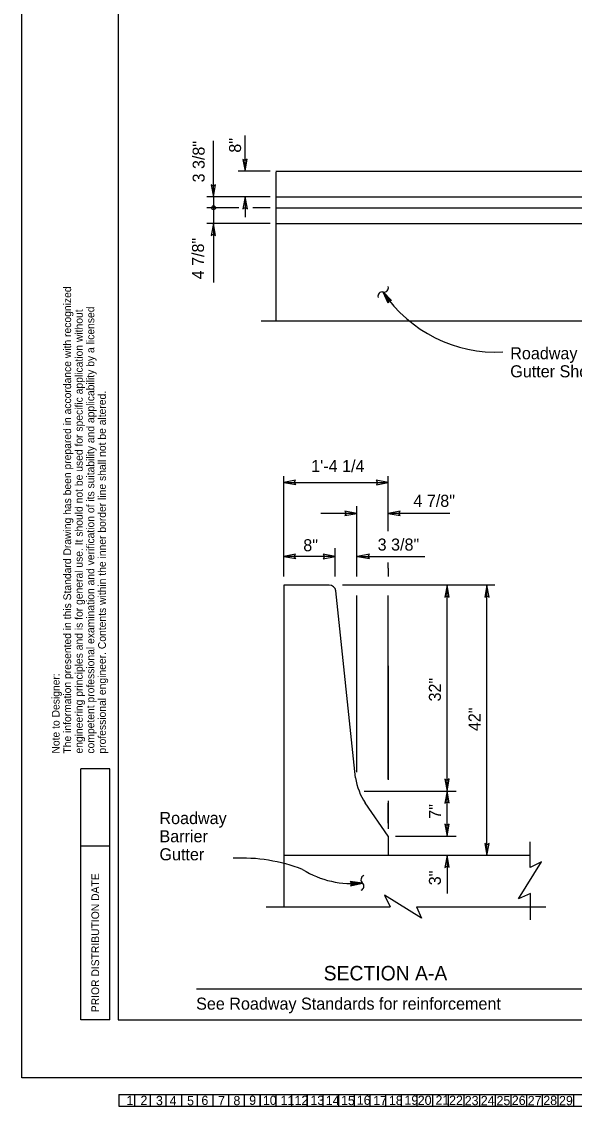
# Model space of a CAD drawing. Extents: x 0 to 2.83, y -0.03 to 1.83.
# Drawn here: x 0 to 0.597, y -0.031 to 1.14 of the extents above; entities that cross this region are included whole.
import ezdxf

# ---------------------------------------------------------------- set-up
doc = ezdxf.new("R2010")
doc.units = 0
for name, color, linetype in [('1', 7, 'Continuous'), ('10', 7, 'Continuous'), ('11', 7, 'Continuous'), ('12', 7, 'Continuous'), ('13', 7, 'Continuous'), ('14', 7, 'Continuous'), ('15', 7, 'Continuous'), ('16', 7, 'Continuous'), ('17', 7, 'Continuous'), ('18', 7, 'Continuous'), ('19', 7, 'Continuous'), ('2', 7, 'Continuous'), ('20', 7, 'Continuous'), ('21', 7, 'Continuous'), ('22', 7, 'Continuous'), ('23', 7, 'Continuous'), ('24', 7, 'Continuous'), ('25', 7, 'Continuous'), ('26', 7, 'Continuous'), ('27', 7, 'Continuous'), ('28', 7, 'Continuous'), ('29', 7, 'Continuous'), ('3', 7, 'Continuous'), ('4', 7, 'Continuous'), ('40', 7, 'Continuous'), ('5', 7, 'Continuous'), ('50', 7, 'Continuous'), ('54', 7, 'Continuous'), ('55', 7, 'Continuous'), ('57', 7, 'Continuous'), ('6', 7, 'Continuous'), ('62', 7, 'Continuous'), ('63', 7, 'Continuous'), ('7', 7, 'Continuous'), ('8', 7, 'Continuous'), ('9', 7, 'Continuous')]:
    doc.layers.add(name, color=color, linetype=linetype)

msp = doc.modelspace()

# ---------------------------------------------------------------- linework, layer by layer
at = {"layer": '40'}
for p, q in [((0.2743, 0.9785), (0.8822, 0.9785)), ((0.2743, 0.9776), (0.2743, 0.817)), ((0.2743, 0.9507), (0.8822, 0.9507)), ((0.2743, 0.939), (0.8822, 0.939)), ((0.2743, 0.9221), (0.8822, 0.9221))]:
    msp.add_line(p, q, dxfattribs=at)
at = {"layer": '50'}
for p, q in [((0.3322, 0.5317), (0.283, 0.5317)), ((0.283, 0.5317), (0.283, 0.24)), ((0.3604, 0.3238), (0.3391, 0.5255)), ((0.3957, 0.2608), (0.3709, 0.2966)), ((0.3957, 0.2608), (0.3957, 0.24)), ((0.283, 0.24), (0.283, 0.1845)), ((0.549, 0.24), (0.283, 0.24))]:
    msp.add_line(p, q, dxfattribs=at)
for centre, radius, start, end in [((0.3322, 0.5248), 0.00694, 5.8395, 90), ((0.4291, 0.3345), 0.0694, 188.8949, 213.1061)]:
    msp.add_arc(centre, radius, start, end, dxfattribs=at)
at = {"layer": '54'}
for points in [[(0.2413, 0.9785), (0.2436, 0.9915), (0.2413, 0.99), (0.2389, 0.9913)], [(0.207, 0.9507), (0.2094, 0.9637), (0.207, 0.9622), (0.2046, 0.9636)], [(0.2413, 0.9507), (0.2389, 0.9377), (0.2413, 0.9392), (0.2437, 0.9379)], [(0.207, 0.9221), (0.2046, 0.9091), (0.207, 0.9106), (0.2094, 0.9092)], [(0.207, 0.9221), (0.2046, 0.9091), (0.207, 0.9106), (0.2094, 0.9092)], [(0.283, 0.6425), (0.2959, 0.6402), (0.2944, 0.6425), (0.2958, 0.6449)], [(0.3958, 0.6425), (0.3828, 0.6449), (0.3843, 0.6425), (0.383, 0.6401)], [(0.3619, 0.6091), (0.349, 0.6115), (0.3505, 0.6091), (0.3491, 0.6067)], [(0.3958, 0.6091), (0.4088, 0.6067), (0.4073, 0.6091), (0.4086, 0.6115)], [(0.283, 0.5626), (0.2959, 0.5603), (0.2944, 0.5626), (0.2958, 0.565)], [(0.3385, 0.5626), (0.3255, 0.565), (0.327, 0.5626), (0.3257, 0.5602)], [(0.3626, 0.5626), (0.3756, 0.5603), (0.3741, 0.5626), (0.3755, 0.565)], [(0.4594, 0.5317), (0.457, 0.5187), (0.4594, 0.5202), (0.4618, 0.5189)], [(0.5024, 0.5317), (0.5001, 0.5187), (0.5024, 0.5202), (0.5048, 0.5189)], [(0.4594, 0.3095), (0.4617, 0.3225), (0.4594, 0.3209), (0.457, 0.3223)], [(0.4594, 0.3095), (0.457, 0.2965), (0.4594, 0.298), (0.4618, 0.2966)], [(0.4594, 0.2608), (0.4617, 0.2738), (0.4594, 0.2723), (0.457, 0.2737)], [(0.5024, 0.24), (0.5048, 0.253), (0.5024, 0.2515), (0.5, 0.2529)], [(0.4594, 0.24), (0.457, 0.227), (0.4594, 0.2285), (0.4618, 0.2272)]]:
    msp.add_lwpolyline(points, close=True, dxfattribs=at)
at = {"layer": '55'}
for p, q in [((0.207, 0.9507), (0.207, 1.0114)), ((0.2413, 0.9785), (0.2413, 1.0169)), ((0.2684, 0.9785), (0.2338, 0.9785)), ((0.2684, 0.9507), (0.1999, 0.9507)), ((0.207, 0.9507), (0.207, 0.9221)), ((0.2413, 0.9507), (0.2413, 0.9287)), ((0.2344, 0.939), (0.1999, 0.939)), ((0.2684, 0.939), (0.2496, 0.939)), ((0.2684, 0.9221), (0.1999, 0.9221)), ((0.207, 0.9221), (0.207, 0.8583)), ((0.2587, 0.817), (0.6796, 0.817)), ((0.283, 0.5409), (0.283, 0.6493)), ((0.3958, 0.5898), (0.3958, 0.6493)), ((0.283, 0.6425), (0.3958, 0.6425)), ((0.3619, 0.6091), (0.3231, 0.6091)), ((0.3619, 0.5409), (0.3619, 0.617)), ((0.4624, 0.6091), (0.3958, 0.6091)), ((0.3385, 0.5626), (0.283, 0.5626)), ((0.3385, 0.5409), (0.3385, 0.5717)), ((0.3626, 0.5626), (0.4352, 0.5626)), ((0.3958, 0.5499), (0.3958, 0.5561)), ((0.3958, 0.5499), (0.3958, 0.5409)), ((0.5111, 0.5317), (0.3464, 0.5317)), ((0.4594, 0.3095), (0.4594, 0.5317)), ((0.5024, 0.24), (0.5024, 0.5317)), ((0.3619, 0.3297), (0.3619, 0.5205)), ((0.3957, 0.3224), (0.3957, 0.5205)), ((0.3958, 0.4448), (0.3958, 0.3214)), ((0.37, 0.3095), (0.4691, 0.3095)), ((0.4594, 0.2608), (0.4594, 0.3095)), ((0.3957, 0.2749), (0.3957, 0.2965)), ((0.3958, 0.2988), (0.3958, 0.2687)), ((0.4038, 0.2608), (0.4691, 0.2608)), ((0.549, 0.227), (0.549, 0.2546)), ((0.4594, 0.24), (0.4594, 0.1988)), ((0.5366, 0.1932), (0.5614, 0.2332)), ((0.5614, 0.2332), (0.549, 0.227)), ((0.4319, 0.1721), (0.3918, 0.197)), ((0.3918, 0.197), (0.3981, 0.1845)), ((0.5494, 0.199), (0.5366, 0.1932)), ((0.5494, 0.1706), (0.5494, 0.199)), ((0.2639, 0.1845), (0.3981, 0.1845)), ((0.4263, 0.1845), (0.4319, 0.1721)), ((0.4263, 0.1845), (0.5661, 0.1845))]:
    msp.add_line(p, q, dxfattribs=at)
for points in [[(0.3903, 0.8482), (0.3995, 0.8388), (0.3973, 0.8387), (0.392, 0.8457), (0.3965, 0.8381), (0.3956, 0.8361), (0.3903, 0.8481)], [(0.3935, 0.8445), (0.3973, 0.8394), (0.3983, 0.8393), (0.3911, 0.847), (0.3955, 0.8374), (0.3959, 0.8385), (0.3927, 0.8436)], [(0.368, 0.2102), (0.3549, 0.2119), (0.3562, 0.2101), (0.365, 0.2101), (0.3562, 0.2091), (0.3552, 0.2071), (0.368, 0.2102)], [(0.3631, 0.2105), (0.3568, 0.2104), (0.3561, 0.2113), (0.3665, 0.2102), (0.3563, 0.2079), (0.3569, 0.2088), (0.363, 0.2094)]]:
    msp.add_lwpolyline(points, dxfattribs=at)
msp.add_circle((0.2072, 0.939), 0.00214, dxfattribs=at)
for centre, radius, start, end in [((0.3894, 0.8435), 0.0047, 78.7125, 195.1185), ((0.3913, 0.8527), 0.0047, 258.7125, 15.1185), ((0.5124, 0.9305), 0.1473, 214.0105, 272.8594), ((0.2377, 0.0558), 0.1813, 68.7429, 92.9324), ((0.3563, 0.3091), 0.0995, 237.9072, 276.7321), ((0.3711, 0.2138), 0.0047, 112.0894, 228.4955), ((0.3649, 0.2067), 0.0047, 292.0894, 48.4955)]:
    msp.add_arc(centre, radius, start, end, dxfattribs=at)
at = {"layer": '57'}
msp.add_line((0.6748, 0.0958), (0.1888, 0.0958), dxfattribs=at)
at = {"layer": '62'}
for p, q in [((0.1049, -0.018), (1.1717, -0.018)), ((0.1049, -0.018), (0.1049, -0.0307)), ((0.105, -0.0181), (1.1718, -0.0181)), ((0.105, -0.0181), (0.105, -0.0308)), ((0.1219, -0.018), (0.1219, -0.0307)), ((0.1219, -0.0181), (0.1219, -0.0308)), ((0.1388, -0.018), (0.1388, -0.0307)), ((0.1388, -0.0181), (0.1388, -0.0308)), ((0.1557, -0.018), (0.1557, -0.0307)), ((0.1558, -0.0181), (0.1558, -0.0308)), ((0.1727, -0.018), (0.1727, -0.0307)), ((0.1727, -0.0181), (0.1727, -0.0308)), ((0.1896, -0.018), (0.1896, -0.0307)), ((0.1896, -0.0181), (0.1896, -0.0308)), ((0.2065, -0.018), (0.2065, -0.0307)), ((0.2066, -0.0181), (0.2066, -0.0308)), ((0.2235, -0.018), (0.2235, -0.0307)), ((0.2235, -0.0181), (0.2235, -0.0308)), ((0.2404, -0.018), (0.2404, -0.0307)), ((0.2404, -0.0181), (0.2404, -0.0308)), ((0.2573, -0.018), (0.2573, -0.0307)), ((0.2574, -0.0181), (0.2574, -0.0308)), ((0.2743, -0.018), (0.2743, -0.0307)), ((0.2743, -0.0181), (0.2743, -0.0308)), ((0.2912, -0.018), (0.2912, -0.0307)), ((0.2912, -0.0181), (0.2912, -0.0308)), ((0.3081, -0.018), (0.3081, -0.0307)), ((0.3082, -0.0181), (0.3082, -0.0308)), ((0.3251, -0.018), (0.3251, -0.0307)), ((0.3251, -0.0181), (0.3251, -0.0308)), ((0.342, -0.018), (0.342, -0.0307)), ((0.342, -0.0181), (0.342, -0.0308)), ((0.3589, -0.018), (0.3589, -0.0307)), ((0.359, -0.0181), (0.359, -0.0308)), ((0.3759, -0.018), (0.3759, -0.0307)), ((0.3759, -0.0181), (0.3759, -0.0308)), ((0.3928, -0.018), (0.3928, -0.0307)), ((0.3928, -0.0181), (0.3928, -0.0308)), ((0.4097, -0.018), (0.4097, -0.0307)), ((0.4098, -0.0181), (0.4098, -0.0308)), ((0.4267, -0.018), (0.4267, -0.0307)), ((0.4267, -0.0181), (0.4267, -0.0308)), ((0.4436, -0.018), (0.4436, -0.0307)), ((0.4436, -0.0181), (0.4436, -0.0308)), ((0.4605, -0.018), (0.4605, -0.0307)), ((0.4606, -0.0181), (0.4606, -0.0308)), ((0.4775, -0.018), (0.4775, -0.0307)), ((0.4775, -0.0181), (0.4775, -0.0308)), ((0.4944, -0.018), (0.4944, -0.0307)), ((0.4944, -0.0181), (0.4944, -0.0308)), ((0.5113, -0.018), (0.5113, -0.0307)), ((0.5114, -0.0181), (0.5114, -0.0308)), ((0.5283, -0.018), (0.5283, -0.0307)), ((0.5283, -0.0181), (0.5283, -0.0308)), ((0.5452, -0.018), (0.5452, -0.0307)), ((0.5452, -0.0181), (0.5452, -0.0308)), ((0.5621, -0.018), (0.5621, -0.0307)), ((0.5622, -0.0181), (0.5622, -0.0308)), ((0.5791, -0.018), (0.5791, -0.0307)), ((0.5791, -0.0181), (0.5791, -0.0308)), ((0.596, -0.018), (0.596, -0.0307)), ((0.596, -0.0181), (0.596, -0.0308)), ((0.1049, -0.0307), (1.1717, -0.0307)), ((0.105, -0.0308), (1.1718, -0.0308))]:
    msp.add_line(p, q, dxfattribs=at)
at = {"layer": '63'}
for p, q in [((0, 0), (0, 1.8333)), ((0.0638, 0.0624), (0.0638, 0.3333)), ((0.0951, 0.3333), (0.0638, 0.3333)), ((0.0951, 0.0624), (0.0951, 0.3333)), ((0.0951, 0.2499), (0.0638, 0.2499)), ((0.0951, 0.0624), (0.0638, 0.0624)), ((2.8333, 0), (0, 0))]:
    msp.add_line(p, q, dxfattribs=at)
msp.add_lwpolyline([(2.7292, 1.7708), (0.1042, 1.7708), (0.1042, 0.0624), (2.7292, 0.0624)], close=True, dxfattribs=at)

# ---------------------------------------------------------------- texts
at = {"layer": '1'}
for p in [(0.1132, -0.0294), (0.1132, -0.0295)]:
    msp.add_text('1', height=0.01, rotation=360, dxfattribs=at).set_placement(p)
at = {"layer": '10'}
msp.add_text('10', height=0.01, rotation=360, dxfattribs=at).set_placement((0.2605, -0.0293))
msp.add_text('10', height=0.01, rotation=360, dxfattribs=at).set_placement((0.2605, -0.0293))
at = {"layer": '11'}
msp.add_text('11', height=0.01, rotation=360, dxfattribs=at).set_placement((0.2796, -0.0294))
msp.add_text('11', height=0.01, rotation=360, dxfattribs=at).set_placement((0.2796, -0.0294))
at = {"layer": '12'}
msp.add_text('12', height=0.01, rotation=360, dxfattribs=at).set_placement((0.2947, -0.0293))
msp.add_text('12', height=0.01, rotation=360, dxfattribs=at).set_placement((0.2947, -0.0293))
at = {"layer": '13'}
msp.add_text('13', height=0.01, rotation=360, dxfattribs=at).set_placement((0.3118, -0.0293))
msp.add_text('13', height=0.01, rotation=360, dxfattribs=at).set_placement((0.3118, -0.0293))
at = {"layer": '14'}
for p in [(0.3284, -0.0294), (0.3285, -0.0294)]:
    msp.add_text('14', height=0.01, rotation=360, dxfattribs=at).set_placement(p)
at = {"layer": '15'}
msp.add_text('15', height=0.01, rotation=360, dxfattribs=at).set_placement((0.3449, -0.0295))
msp.add_text('15', height=0.01, rotation=360, dxfattribs=at).set_placement((0.3449, -0.0295))
at = {"layer": '16'}
msp.add_text('16', height=0.01, rotation=360, dxfattribs=at).set_placement((0.3619, -0.0292))
msp.add_text('16', height=0.01, rotation=360, dxfattribs=at).set_placement((0.3619, -0.0292))
at = {"layer": '17'}
msp.add_text('17', height=0.01, rotation=360, dxfattribs=at).set_placement((0.3797, -0.0295))
msp.add_text('17', height=0.01, rotation=360, dxfattribs=at).set_placement((0.3797, -0.0295))
at = {"layer": '18'}
msp.add_text('18', height=0.01, rotation=360, dxfattribs=at).set_placement((0.3966, -0.0294))
msp.add_text('18', height=0.01, rotation=360, dxfattribs=at).set_placement((0.3966, -0.0294))
at = {"layer": '19'}
msp.add_text('19', height=0.01, rotation=360, dxfattribs=at).set_placement((0.4134, -0.0292))
msp.add_text('19', height=0.01, rotation=360, dxfattribs=at).set_placement((0.4134, -0.0292))
at = {"layer": '2'}
msp.add_text('2', height=0.01, rotation=360, dxfattribs=at).set_placement((0.1283, -0.0293))
msp.add_text('2', height=0.01, rotation=360, dxfattribs=at).set_placement((0.1283, -0.0293))
at = {"layer": '20'}
for p in [(0.4277, -0.0293), (0.4278, -0.0293)]:
    msp.add_text('20', height=0.01, rotation=360, dxfattribs=at).set_placement(p)
at = {"layer": '21'}
msp.add_text('21', height=0.01, rotation=360, dxfattribs=at).set_placement((0.4469, -0.0291))
msp.add_text('21', height=0.01, rotation=360, dxfattribs=at).set_placement((0.4469, -0.0291))
at = {"layer": '22'}
msp.add_text('22', height=0.01, rotation=360, dxfattribs=at).set_placement((0.4616, -0.0293))
msp.add_text('22', height=0.01, rotation=360, dxfattribs=at).set_placement((0.4616, -0.0293))
at = {"layer": '23'}
msp.add_text('23', height=0.01, rotation=360, dxfattribs=at).set_placement((0.4785, -0.0296))
msp.add_text('23', height=0.01, rotation=360, dxfattribs=at).set_placement((0.4785, -0.0296))
at = {"layer": '24'}
msp.add_text('24', height=0.01, rotation=360, dxfattribs=at).set_placement((0.4958, -0.0296))
msp.add_text('24', height=0.01, rotation=360, dxfattribs=at).set_placement((0.4958, -0.0296))
at = {"layer": '25'}
msp.add_text('25', height=0.01, rotation=360, dxfattribs=at).set_placement((0.5128, -0.0296))
msp.add_text('25', height=0.01, rotation=360, dxfattribs=at).set_placement((0.5128, -0.0296))
at = {"layer": '26'}
msp.add_text('26', height=0.01, rotation=360, dxfattribs=at).set_placement((0.5293, -0.0294))
msp.add_text('26', height=0.01, rotation=360, dxfattribs=at).set_placement((0.5293, -0.0294))
at = {"layer": '27'}
msp.add_text('27', height=0.01, rotation=360, dxfattribs=at).set_placement((0.5465, -0.0296))
msp.add_text('27', height=0.01, rotation=360, dxfattribs=at).set_placement((0.5465, -0.0296))
at = {"layer": '28'}
msp.add_text('28', height=0.01, rotation=360, dxfattribs=at).set_placement((0.5633, -0.0294))
msp.add_text('28', height=0.01, rotation=360, dxfattribs=at).set_placement((0.5633, -0.0294))
at = {"layer": '29'}
msp.add_text('29', height=0.01, rotation=360, dxfattribs=at).set_placement((0.5803, -0.0296))
msp.add_text('29', height=0.01, rotation=360, dxfattribs=at).set_placement((0.5803, -0.0296))
at = {"layer": '3'}
for p in [(0.145, -0.0295), (0.145, -0.0296)]:
    msp.add_text('3', height=0.01, rotation=360, dxfattribs=at).set_placement(p)
at = {"layer": '4'}
for p in [(0.1597, -0.0298), (0.1597, -0.0299)]:
    msp.add_text('4', height=0.01, rotation=360, dxfattribs=at).set_placement(p)
at = {"layer": '5'}
msp.add_text('5', height=0.01, rotation=360, dxfattribs=at).set_placement((0.1786, -0.0298))
msp.add_text('5', height=0.01, rotation=360, dxfattribs=at).set_placement((0.1786, -0.0298))
at = {"layer": '57'}
for s, p in [('3 3/8"', (0.1976, 0.9664)), ('8"', (0.2369, 0.9985)), ('4 7/8"', (0.1969, 0.8618)), ('32"', (0.4527, 0.4062)), ('42"', (0.4955, 0.3742)), ('7"', (0.4527, 0.2796)), ('3"', (0.4527, 0.2078))]:
    msp.add_text(s, height=0.01297, rotation=90, dxfattribs=at).set_placement(p)
for s, height, p in [('Roadway Barrier', 0.013025, (0.5276, 0.7755)), ('Gutter Shown', 0.013025, (0.5276, 0.756)), ("1'-4 1/4", 0.01302, (0.3127, 0.6538)), ('4 7/8" ', 0.01302, (0.423, 0.6162)), ('8"', 0.01302, (0.3041, 0.5683)), ('3 3/8"', 0.01302, (0.3844, 0.569)), ('Roadway', 0.01302, (0.1488, 0.2738)), ('Barrier', 0.01302, (0.1488, 0.2542)), ('Gutter', 0.01302, (0.1488, 0.2347)), ('SECTION A-A', 0.015625, (0.3261, 0.1051)), ('See Roadway Standards for reinforcement', 0.013021, (0.1884, 0.0735))]:
    msp.add_text(s, height=height, dxfattribs=at).set_placement(p)
at = {"layer": '6'}
msp.add_text('6', height=0.01, rotation=360, dxfattribs=at).set_placement((0.1941, -0.0294))
msp.add_text('6', height=0.01, rotation=360, dxfattribs=at).set_placement((0.1941, -0.0294))
at = {"layer": '62'}
for s, height, p in [('The information presented in this Standard Drawing has been prepared in accordance with recognized', 0.008333, (0.0534, 0.3499)), ('competent professional examination and verification of its suitability and applicability by a licensed', 0.0083333, (0.0784, 0.3499)), ('engineering principles and is for general use. It should not be used for specific application without', 0.0083333, (0.0659, 0.3499)), ('professional engineer. Contents within the inner border line shall not be altered.', 0.008333, (0.0909, 0.3499)), ('Note to Designer:', 0.008333, (0.0409, 0.3499))]:
    msp.add_text(s, height=height, rotation=90, dxfattribs=at).set_placement(p)
at = {"layer": '63'}
msp.add_text('PRIOR DISTRIBUTION DATE', height=0.008333, rotation=90, dxfattribs=at).set_placement((0.0836, 0.0708))
at = {"layer": '7'}
for p in [(0.2121, -0.0296), (0.2121, -0.0297)]:
    msp.add_text('7', height=0.01, rotation=360, dxfattribs=at).set_placement(p)
at = {"layer": '8'}
msp.add_text('8', height=0.01, rotation=360, dxfattribs=at).set_placement((0.2287, -0.0296))
msp.add_text('8', height=0.01, rotation=360, dxfattribs=at).set_placement((0.2287, -0.0296))
at = {"layer": '9'}
for p in [(0.2457, -0.0292), (0.2457, -0.0293)]:
    msp.add_text('9', height=0.01, rotation=360, dxfattribs=at).set_placement(p)

doc.saveas('drawing.dxf')
